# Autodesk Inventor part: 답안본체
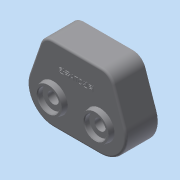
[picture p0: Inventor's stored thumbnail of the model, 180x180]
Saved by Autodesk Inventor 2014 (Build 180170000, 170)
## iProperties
Created: 2014-12
Part Number: 답안본체
Material: 일반
Document SubType Name: Modeling
Designer: user
Density: 1 g/cm^3
Appearance: 기본값
Author: user
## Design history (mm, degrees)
sketch "스케치1"
  geometry: L1 (-47, 0)-(47, 0); L2 (47, 0)-(66.565, -56.803); L3 (-47, 0)-(-66.565, -56.803); L4 (-32.527, -104.527)-(32.527, -104.527); L5 (-32.527, -68.527)-(0, -36); L6 (0, -36)-(32.527, -68.527); L7 (0, -36)-(0, -104.527); C1 r 24 at (0, -36); C2 r 24 at (-32.527, -68.527); C3 r 24 at (32.527, -68.527); A1 r 36 centre (32.527, -68.527) between (32.527, -104.527) and (66.565, -56.803); A2 r 36 centre (-32.527, -68.527) between (-66.565, -56.803) and (-32.527, -104.527); A3 r 46 centre (0, -36) between (32.527, -68.527) and (-32.527, -68.527); 2 further points
  constraints: 14 end point, 6 centre point, 6 point on circle, 5 coincident, 4 tangent, 2 midpoint, 1 horizontal, 1 horizontal alignment, 1 parallel, 1 perpendicular, 1 vertical alignment
  dimensions: "d0" = 36 radius of A2; "d1" = 94 distance of L1.start L1.end; "d2" = 36 distance from line of L6.end L4; "d5" = 92 diameter of A3; "d6" = 90 deg angle of L5 L6; "d7" = 48 diameter of C2; "d8" = 48 diameter of C3; "d9" = 48 diameter of C1; "d10" = 36 distance from line of L5.end L1
extrude "돌출1" new body sketch "스케치1" distance "d11" = 10; taper "d12" = 0 deg
node "작업 평면1"
sketch "스케치2"
  geometry: L1 (11.723, 10)-(-36, 10) reference; L2 (-20, 10)-(-18.766, 17); L3 (-18.766, 17)-(18.766, 17); L4 (68.527, 10)-(11.723, 10) reference; L5 (18.766, 17)-(20, 10); L6 (0, 0)-(0, 22.754); L7 (-36, 0)-(-36, 10) reference; L8 (0, 17)-(0, 10); L9 (0, 10)-(20, 10); 1 further point
  constraints: 12 end point, 5 point on line, 1 collinear, 1 midpoint, 1 parallel, 1 perpendicular
  dimensions: "d13" = 100 deg angle of L1 L2; "d14" = 100 deg angle of L4 L5; "d15" = 40 distance of L2.start L5.end; "d16" = 7 distance between parallel lines of L1 L3; "d17" = 36 distance between parallel lines of L7 L6
revolve "회전1" sketch "스케치2" stored, may be unused: angle "d18" = 90 deg
extrude "돌출2" join sketch "스케치1" distance "d19" = 34; taper "d20" = 0 deg
sketch "스케치3"
  geometry: C1 r 18.766 at (0, 0) reference; C2 r 18.766 at (-65.054, 0) reference; 3 further points
  constraints: 2 coincident
hole "구멍1" sketch "스케치3" at (0, 0), (-65.054, 0) diameter "d21" = 15.5; stored, may be unused: countersink angle "d25" = 90 deg, drill point angle "d27" = 0 deg; dims "d22" = 6, "d23" = 30, "d24" = 7, "d26" = 17
sketch "스케치4"
  geometry: L1 (66.565, -56.803)-(47, 0) reference; L2 (47, 0)-(-47, 0) reference; L3 (-47, 0)-(-66.565, -56.803) reference; L4 (-32.527, -104.527)-(32.527, -104.527) reference; L5 (-43.434, -5)-(43.434, -5); L6 (43.434, -5)-(61.837, -58.432); L7 (32.527, -99.527)-(-32.527, -99.527); L8 (-61.837, -58.432)-(-43.434, -5); A1 r 36 centre (-32.527, -68.527) between (-66.565, -56.803) and (-32.527, -104.527) reference; A2 r 36 centre (32.527, -68.527) between (32.527, -104.527) and (66.565, -56.803) reference; A3 r 31 centre (32.527, -68.527) between (32.527, -99.527) and (61.837, -58.432); A4 r 31 centre (-32.527, -68.527) between (-61.837, -58.432) and (-32.527, -99.527); 1 further point
  constraints: 8 end point, 4 point on circle, 2 centre point, 5 other
  dimensions: "d28" = 5 distance between parallel lines of L2 L5
extrude "돌출3" cut sketch "스케치4" distance "d29" = 23; taper "d30" = 0 deg
fillet "모깎기1" dims "d31" = 18
fillet "모깎기2" dims "d32" = 18
sketch "스케치5"
  geometry: L1 (-30.596, -5)-(30.596, -5) reference; L2 (-61.837, -58.432)-(-47.615, -17.138) reference; L3 (32.527, -99.527)-(-32.527, -99.527) reference; L4 (47.615, -17.138)-(61.837, -58.432) reference; A1 r 18 centre (30.596, -23) between (47.615, -17.138) and (30.596, -5) reference; A2 r 18 centre (-30.596, -23) between (-30.596, -5) and (-47.615, -17.138) reference; A3 r 31 centre (-32.527, -68.527) between (-61.837, -58.432) and (-32.527, -99.527) reference; A4 r 31 centre (32.527, -68.527) between (32.527, -99.527) and (61.837, -58.432) reference; 3 further points
  constraints: 2 coincident
hole "구멍2" sketch "스케치5" at (32.527, -68.527), (-32.527, -68.527) diameter "d33" = 35; stored, may be unused: countersink angle "d37" = 90 deg, drill point angle "d39" = 0 deg; dims "d34" = 6, "d35" = 30, "d36" = 7, "d38" = 11
sketch "스케치6"
  geometry: L1 (-30.596, -5)-(30.596, -5) reference; L2 (-61.837, -58.432)-(-47.615, -17.138) reference; L3 (32.527, -99.527)-(-32.527, -99.527) reference; L4 (47.615, -17.138)-(61.837, -58.432) reference; L5 (34.162, 0)-(-34.162, 0) reference; C1 r 17.5 at (32.527, -68.527) reference; C2 r 17.5 at (-32.527, -68.527) reference; A1 r 18 centre (30.596, -23) between (47.615, -17.138) and (30.596, -5) reference; A2 r 18 centre (-30.596, -23) between (-30.596, -5) and (-47.615, -17.138) reference; A3 r 31 centre (-32.527, -68.527) between (-61.837, -58.432) and (-32.527, -99.527) reference; A4 r 31 centre (32.527, -68.527) between (32.527, -99.527) and (61.837, -58.432) reference; A5 r 24 centre (-32.527, -68.527) between (-21.111, -47.416) and (-11.416, -57.111); A6 r 24 centre (32.527, -68.527) between (11.416, -57.111) and (21.111, -47.416); A7 r 24 centre (0, -36) between (21.111, -47.416) and (-21.111, -47.416); A8 r 24 centre (0, -36) between (-11.416, -57.111) and (11.416, -57.111); 2 further points
  constraints: 8 point on circle, 4 centre point, 2 coincident, 1 equal radius, 1 midpoint, 1 vertical alignment
  dimensions: "d40" = 48 diameter of A5; "d42" = 36 distance from line of A7.centre L5; "d43" = 24 radius of A7; "d44" = 24 radius of A8
extrude "돌출4" cut sketch "스케치6" distance "d45" = 11; taper "d46" = 0 deg
sketch "스케치7"
  geometry: C1 r 17.5 at (32.527, -68.527) reference; C2 r 17.5 at (-32.527, -68.527) reference; A1 r 24 centre (0, -36) between (21.111, -47.416) and (-21.111, -47.416) reference; A2 r 24 centre (-32.527, -68.527) between (-21.111, -47.416) and (-11.416, -57.111) reference; A3 r 24 centre (0, -36) between (-11.416, -57.111) and (11.416, -57.111) reference; A4 r 24 centre (32.527, -68.527) between (11.416, -57.111) and (21.111, -47.416) reference; 2 further points
  constraints: 1 coincident
hole "구멍3" sketch "스케치7" at (0, -36) diameter "d47" = 20; stored, may be unused: countersink angle "d51" = 90 deg, drill point angle "d53" = 0 deg; dims "d48" = 6, "d49" = 40, "d50" = 12, "d52" = 15
sketch "스케치8"
  geometry: L1 (-61.837, -58.432)-(-47.615, -17.138) reference; L2 (-30.596, -5)-(30.596, -5) reference; L3 (47.615, -17.138)-(61.837, -58.432) reference; L4 (32.527, -99.527)-(-32.527, -99.527) reference; L5 (-51.181, -12.138)-(-66.565, -56.803) reference; L6 (-32.527, -104.527)-(32.527, -104.527) reference; L7 (66.565, -56.803)-(51.181, -12.138) reference; L8 (34.162, 0)-(-34.162, 0) reference; L9 (47.615, -17.138)-(61.837, -58.432) reference; A1 r 18 centre (-30.596, -23) between (-30.596, -5) and (-47.615, -17.138) reference; A2 r 18 centre (30.596, -23) between (47.615, -17.138) and (30.596, -5) reference; A3 r 31 centre (32.527, -68.527) between (32.527, -99.527) and (61.837, -58.432) reference; A4 r 31 centre (-32.527, -68.527) between (-61.837, -58.432) and (-32.527, -99.527) reference; A5 r 18 centre (-34.162, -18) between (-34.162, 0) and (-51.181, -12.138) reference; A6 r 36 centre (-32.527, -68.527) between (-66.565, -56.803) and (-32.527, -104.527) reference; A7 r 36 centre (32.527, -68.527) between (32.527, -104.527) and (66.565, -56.803) reference; A8 r 18 centre (34.162, -18) between (51.181, -12.138) and (34.162, 0) reference; A9 r 8 centre (51.7, -29) between (49.095, -21.436) and (54.305, -36.564); 1 further point
  constraints: 3 point on line, 2 point on circle, 1 centre point
  dimensions: "d55" = 8 radius of A9; "d95" = 29 distance from line of A9.centre L8
extrude "돌출5" join sketch "스케치8" stored distance "d56" = 11; taper "d57" = 0 deg
sketch "스케치9"
  geometry: L1 (-51.181, -12.138)-(-66.565, -56.803) reference; L2 (-32.527, -104.527)-(32.527, -104.527) reference; L3 (66.565, -56.803)-(51.181, -12.138) reference; L4 (34.162, 0)-(-34.162, 0) reference; L5 (54.305, -36.564)-(61.837, -58.432) reference; L6 (32.527, -99.527)-(-32.527, -99.527) reference; L7 (-61.837, -58.432)-(-54.305, -36.564) reference; L8 (-49.095, -21.436)-(-47.615, -17.138) reference; L9 (-30.596, -5)-(30.596, -5) reference; L10 (47.615, -17.138)-(49.095, -21.436) reference; L11 (32.527, -99.527)-(-32.527, -99.527) reference; A1 r 18 centre (-34.162, -18) between (-34.162, 0) and (-51.181, -12.138) reference; A2 r 36 centre (-32.527, -68.527) between (-66.565, -56.803) and (-32.527, -104.527) reference; A3 r 36 centre (32.527, -68.527) between (32.527, -104.527) and (66.565, -56.803) reference; A4 r 18 centre (34.162, -18) between (51.181, -12.138) and (34.162, 0) reference; A5 r 8 centre (51.7, -29) between (49.095, -21.436) and (54.305, -36.564) reference; A6 r 31 centre (32.527, -68.527) between (32.527, -99.527) and (61.837, -58.432) reference; A7 r 31 centre (-32.527, -68.527) between (-61.837, -58.432) and (-32.527, -99.527) reference; A8 r 8 centre (-51.7, -29) between (-54.305, -36.564) and (-49.095, -21.436) reference; A9 r 18 centre (-30.596, -23) between (-30.596, -5) and (-47.615, -17.138) reference; A10 r 18 centre (30.596, -23) between (47.615, -17.138) and (30.596, -5) reference; A11 r 8 centre (0, -99.527) between (8, -99.527) and (-8, -99.527); 3 further points
  constraints: 3 point on circle, 2 midpoint, 2 point on line, 1 centre point, 1 vertical alignment
  dimensions: "d58" = 8 radius of A11
extrude "돌출6" join sketch "스케치9" stored distance "d59" = 11; taper "d60" = 0 deg
sketch "스케치10"
  geometry: L1 (-51.181, -12.138)-(-66.565, -56.803) reference; L2 (-32.527, -104.527)-(32.527, -104.527) reference; L3 (66.565, -56.803)-(51.181, -12.138) reference; L4 (34.162, 0)-(-34.162, 0) reference; L5 (-8, -99.527)-(-32.527, -99.527) reference; L6 (-61.837, -58.432)-(-54.305, -36.564) reference; L7 (-49.095, -21.436)-(-47.615, -17.138) reference; L8 (-30.596, -5)-(30.596, -5) reference; L9 (47.615, -17.138)-(49.095, -21.436) reference; L10 (54.305, -36.564)-(61.837, -58.432) reference; L11 (32.527, -99.527)-(8, -99.527) reference; A1 r 18 centre (-34.162, -18) between (-34.162, 0) and (-51.181, -12.138) reference; A2 r 36 centre (-32.527, -68.527) between (-66.565, -56.803) and (-32.527, -104.527) reference; A3 r 36 centre (32.527, -68.527) between (32.527, -104.527) and (66.565, -56.803) reference; A4 r 18 centre (34.162, -18) between (51.181, -12.138) and (34.162, 0) reference; A5 r 8 centre (0, -99.527) between (8, -99.527) and (-8, -99.527) reference; A6 r 31 centre (-32.527, -68.527) between (-61.837, -58.432) and (-32.527, -99.527) reference; A7 r 8 centre (-51.7, -29) between (-54.305, -36.564) and (-49.095, -21.436) reference; A8 r 18 centre (-30.596, -23) between (-30.596, -5) and (-47.615, -17.138) reference; A9 r 18 centre (30.596, -23) between (47.615, -17.138) and (30.596, -5) reference; A10 r 8 centre (51.7, -29) between (49.095, -21.436) and (54.305, -36.564) reference; A11 r 31 centre (32.527, -68.527) between (32.527, -99.527) and (61.837, -58.432) reference; 4 further points
  constraints: 3 coincident
hole "구멍4" sketch "스케치10" at (-51.7, -29), (51.7, -29), (0, -99.527) diameter "d61" = 4.134; stored, may be unused: countersink angle "d65" = 90 deg, drill point angle "d67" = 118 deg; dims "d62" = 20, "d63" = 40, "d64" = 12, "d66" = 23
fillet "모깎기3" dims "d68" = 3
fillet "모깎기4" dims "d69" = 3
fillet "모깎기5" dims "d70" = 3
fillet "모깎기6" dims "d71" = 3
fillet "모깎기7" dims "d72" = 3
fillet "모깎기8" dims "d73" = 0.3
fillet "모깎기9" dims "d74" = 3
fillet "모깎기10" dims "d75" = 0.3
fillet "모깎기11" dims "d76" = 0.1
chamfer "모따기1" distance "d77" = 1; stored, may be unused: second distance "d78" = 2, angle "d79" = 45 deg
chamfer "모따기2" distance "d80" = 1; stored, may be unused: second distance "d81" = 2, angle "d82" = 45 deg
chamfer "모따기3" distance "d83" = 1; stored, may be unused: second distance "d84" = 2, angle "d85" = 45 deg
chamfer "모따기4" distance "d86" = 1; stored, may be unused: second distance "d87" = 2, angle "d88" = 45 deg
chamfer "모따기5" distance "d89" = 1; stored, may be unused: second distance "d90" = 2, angle "d91" = 45 deg
sketch "스케치11"
  geometry: 2 further points
  constraints: 1 vertical alignment, 1 other
  dimensions: "d92" = 30 distance of point (0, -30) point (0, 0)
feature "엠보싱1" sketch "스케치11" dims "d93" = 1, "d94" = 0
node "솔리드1"
mirror "대칭1"
mirror "대칭2"
node "투영된 루프1"
node "투영된 루프2"
node "투영된 루프3"
node "투영된 루프4"
node "투영된 루프5"
node "투영된 루프6"
node "투영된 루프7"
node "투영된 루프8"
node "투영된 루프9"
other parameters: "d41" = 48
